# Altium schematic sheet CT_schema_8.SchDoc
size 274 x 160 mm
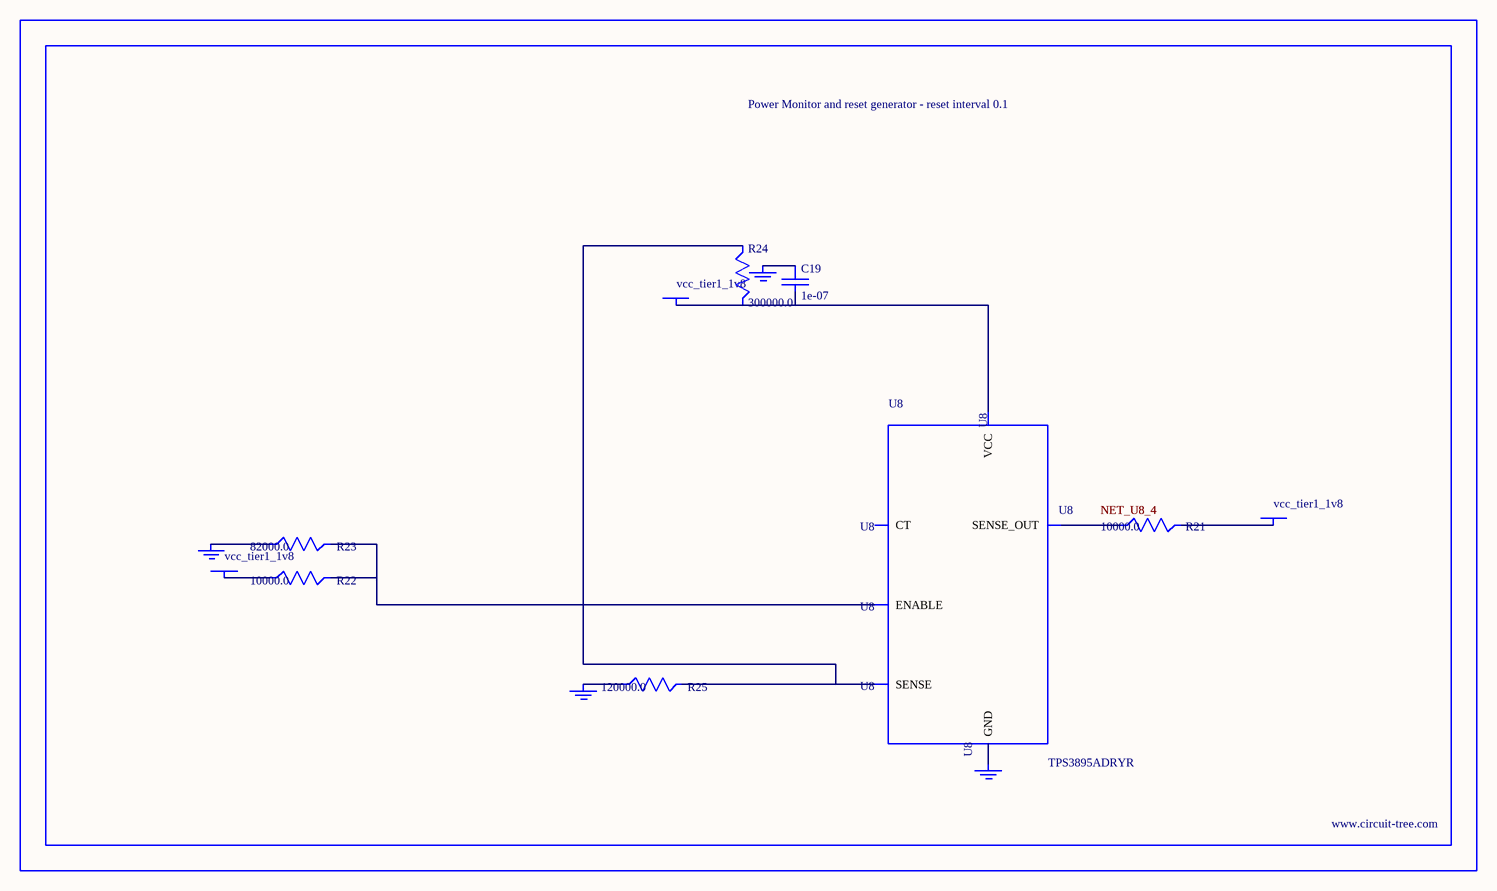
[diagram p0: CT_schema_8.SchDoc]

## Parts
BORDER7  (no value)
C19  1e-07  [C0402]
GND_INSTANCE_7_0  (no value)
GND_INSTANCE_7_1  (no value)
GND_INSTANCE_7_2  (no value)
GND_INSTANCE_7_3  (no value)
POWER_INSTANCE_7_0  vcc_tier1_1v8
POWER_INSTANCE_7_1  vcc_tier1_1v8
POWER_INSTANCE_7_2  vcc_tier1_1v8
R21  10000.0  [R0603]
R22  10000.0  [R0603]
R23  82000.0  [R0603]
R24  300000.0  [R0603]
R25  120000.0  [R0603]
U8  TPS3895ADRYR  [SON-6]

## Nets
NetC19_1: C19.1 GND_INSTANCE_7_2.0(GND)
NetC19_2: C19.2 POWER_INSTANCE_7_2.0(PWR) R24.2 U8.6(VCC)
NetGND_INSTANCE_7_0_0: GND_INSTANCE_7_0.0(GND) R23.1
NetGND_INSTANCE_7_1_0: GND_INSTANCE_7_1.0(GND) R25.1
NetGND_INSTANCE_7_3_0: GND_INSTANCE_7_3.0(GND) U8.2(GND)
NetPOWER_INSTANCE_7_0_0: POWER_INSTANCE_7_0.0(PWR) R22.1
NetPOWER_INSTANCE_7_1_0: POWER_INSTANCE_7_1.0(PWR) R21.2
NetR21_1: R21.1 U8.4(SENSE_OUT)
NetR22_2: R22.2 R23.2 U8.1(ENABLE)
NetR24_1: R24.1 R25.2 U8.3(SENSE)

Not connected (* = marked no-connect by the designer): U8 5(CT)

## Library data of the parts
BORDER7 = BORDER_PAGE7
C19 = C0402C104K3RACTU
GND_INSTANCE_7_0-GND_INSTANCE_7_3 = GND
POWER_INSTANCE_7_0-POWER_INSTANCE_7_2 = PWR
R21 R22 = RC0603JR-0710KL
R23 = RC0603JR-0782KL
R24 = RC0603JR-07300KL
R25 = RC0603JR-07120KL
